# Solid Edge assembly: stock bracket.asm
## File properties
Author: Deepak Maini
Template: normal.asm
Last saved by: CADCIM
Revision: 6
Application: Solid Edge
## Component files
adjusting_nut_handle.par
adjusting_screw_guide.par
Stock_support_base.par
thrust_bearing.par
adjusting_screw_nut.par
support_adjusting_screw.par
support_roller_bracket.par
stock_support_roller.par
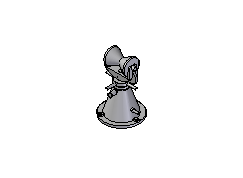
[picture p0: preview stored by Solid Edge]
